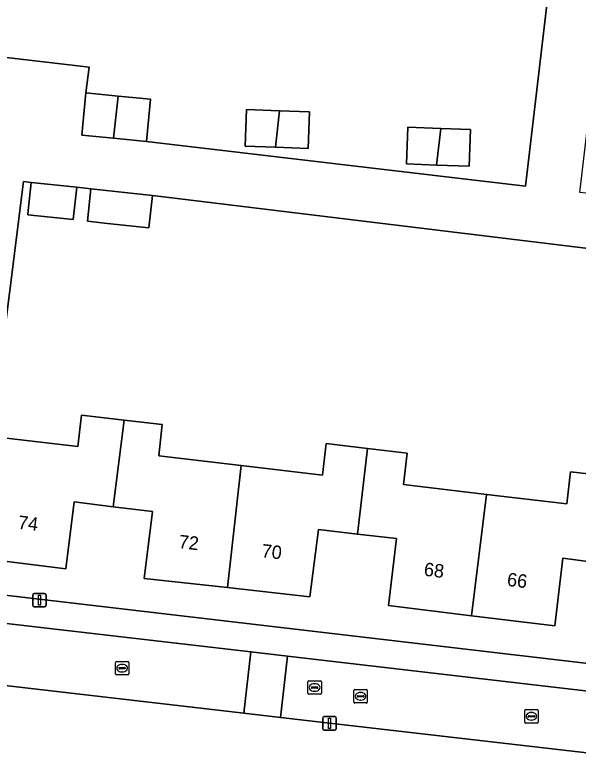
# Model space of a CAD drawing. Extents: x 161241 to 161758, y 384138 to 384885.
# Drawn here: x 161418.6 to 161460.5, y 384342.9 to 384397.6 of the extents above; entities that cross this region are included whole.
import ezdxf

# ---------------------------------------------------------------- set-up
doc = ezdxf.new("R2010")
doc.units = 0
for name, color, linetype in [('IMGEO_Erf', 7, 'Continuous'), ('IMGEO_Kolk', 7, 'Continuous'), ('IMGEO_Lichtmast', 7, 'Continuous'), ('IMGEO_Pand', 7, 'Continuous'), ('IMGEO_Pand_nummerreeks', 7, 'Continuous'), ('IMGEO_Rijbaan_lokaal_open', 7, 'Continuous'), ('IMGEO_Rioolput', 7, 'Continuous'), ('IMGEO_Voetpad_open', 7, 'Continuous')]:
    doc.layers.add(name, color=color, linetype=linetype)

msp = doc.modelspace()

# ---------------------------------------------------------------- linework, layer by layer
at = {"layer": 'IMGEO_Erf'}
for points in [[(161415.847, 384394.67), (161424.15, 384393.701), (161423.913, 384391.799), (161426.306, 384391.565), (161428.717, 384391.33), (161428.41, 384388.19), (161456.596, 384384.852), (161460.391, 384417.148), (161459.347, 384417.271), (161457.727, 384415.687), (161417.974, 384420.297)], [(161472.875, 384378.82), (161428.856, 384384.157), (161428.597, 384381.761), (161425.529, 384382.092), (161424.024, 384382.255), (161424.284, 384384.664), (161423.233, 384384.777), (161422.973, 384382.369), (161419.593, 384382.735), (161419.599, 384382.791), (161419.853, 384385.142), (161419.263, 384385.217), (161417.156, 384368.588)], [(161417.35, 384366.195), (161423.302, 384365.497), (161423.576, 384367.831), (161426.756, 384367.458), (161429.595, 384367.125), (161429.323, 384364.801), (161435.447, 384364.083), (161441.5, 384363.373), (161441.774, 384365.707), (161444.836, 384365.348), (161447.793, 384365.001), (161447.518, 384362.658), (161453.697, 384361.933), (161459.665, 384361.233), (161459.945, 384363.617), (161463.005, 384363.258)], [(161464.974, 384356.457), (161462.172, 384356.819), (161459.371, 384357.18), (161458.786, 384352.151), (161452.591, 384352.91), (161446.419, 384353.667), (161447.01, 384358.643), (161444.102, 384358.98), (161441.194, 384359.316), (161440.559, 384354.315), (161434.437, 384354.996), (161428.239, 384355.685), (161428.857, 384360.656), (161425.952, 384361.017), (161423.051, 384361.378), (161422.432, 384356.406), (161416.255, 384357.153)], [(161394.009, 384357.23), (161490.429, 384345.932)], [(161464.362, 384342.323), (161438.38, 384345.338), (161435.648, 384345.655), (161391.147, 384350.82), (161389.324, 384351.032), (161386.343, 384326.184)]]:
    msp.add_lwpolyline(points, dxfattribs=at)
for points in [[(161440.426, 384387.665), (161438.007, 384387.754), (161435.762, 384387.838), (161435.863, 384390.564), (161438.314, 384390.473), (161440.527, 384390.391)], [(161449.988, 384386.426), (161447.743, 384386.51), (161447.844, 384389.236), (161450.295, 384389.145), (161452.508, 384389.063), (161452.407, 384386.337)]]:
    msp.add_lwpolyline(points, close=True, dxfattribs=at)
at = {"layer": 'IMGEO_Kolk'}
for p, q in [((161426.105, 384348.579), (161426.105, 384349.431)), ((161426.18, 384349.505), (161427.032, 384349.505)), ((161426.593, 384349.285), (161426.618, 384349.285)), ((161427.106, 384349.431), (161427.106, 384348.579)), ((161426.364, 384348.999), (161426.364, 384349.011)), ((161426.802, 384348.962), (161426.404, 384348.962)), ((161426.407, 384349.048), (161426.805, 384349.048)), ((161426.616, 384348.725), (161426.591, 384348.725)), ((161426.848, 384349.011), (161426.848, 384348.999)), ((161427.032, 384348.505), (161426.18, 384348.505)), ((161443.833, 384346.488), (161443.833, 384347.34)), ((161443.908, 384347.414), (161444.76, 384347.414)), ((161444.321, 384347.194), (161444.346, 384347.194)), ((161444.834, 384347.34), (161444.834, 384346.488)), ((161444.092, 384346.908), (161444.092, 384346.92)), ((161444.53, 384346.871), (161444.132, 384346.871)), ((161444.135, 384346.957), (161444.533, 384346.957)), ((161444.344, 384346.634), (161444.319, 384346.634)), ((161444.576, 384346.92), (161444.576, 384346.908)), ((161444.76, 384346.414), (161443.908, 384346.414)), ((161456.608, 384345.926), (161457.46, 384345.926)), ((161456.533, 384345), (161456.533, 384345.852)), ((161456.792, 384345.42), (161456.792, 384345.432)), ((161457.23, 384345.383), (161456.832, 384345.383)), ((161456.835, 384345.469), (161457.233, 384345.469)), ((161457.021, 384345.706), (161457.046, 384345.706)), ((161457.276, 384345.432), (161457.276, 384345.42)), ((161457.534, 384345.852), (161457.534, 384345)), ((161457.46, 384344.926), (161456.608, 384344.926)), ((161457.044, 384345.146), (161457.019, 384345.146))]:
    msp.add_line(p, q, dxfattribs=at)
for points in [[(161426.105, 384348.579), (161426.105, 384349.431)], [(161426.18, 384349.505), (161427.032, 384349.505)], [(161427.106, 384349.431), (161427.106, 384348.579)], [(161427.032, 384348.505), (161426.18, 384348.505)], [(161443.833, 384346.488), (161443.833, 384347.34)], [(161443.908, 384347.414), (161444.76, 384347.414)], [(161444.834, 384347.34), (161444.834, 384346.488)], [(161444.76, 384346.414), (161443.908, 384346.414)], [(161456.608, 384345.926), (161457.46, 384345.926)], [(161456.533, 384345), (161456.533, 384345.852)], [(161457.534, 384345.852), (161457.534, 384345)], [(161457.46, 384344.926), (161456.608, 384344.926)]]:
    msp.add_lwpolyline(points, dxfattribs=at)
for centre, radius, start, end in [((161426.182, 384349.429), 0.0765, 91.552, 178.448), ((161426.182, 384349.429), 0.0765, 91.552, 178.448), ((161427.03, 384349.429), 0.0765, 1.552, 88.448), ((161427.03, 384349.429), 0.0765, 1.552, 88.448), ((161426.404, 384349.008), 0.0403, 85.8775, 175.7526), ((161426.401, 384348.998), 0.0366, 178.938, 274.7102), ((161426.805, 384349.005), 0.043, 264.8664, 352.4533), ((161426.809, 384349.01), 0.0386, 1.7309, 96.639), ((161426.182, 384348.581), 0.0765, 181.552, 268.448), ((161426.182, 384348.581), 0.0765, 181.552, 268.448), ((161427.03, 384348.581), 0.0765, 271.552, 358.448), ((161427.03, 384348.581), 0.0765, 271.552, 358.448), ((161443.91, 384347.338), 0.0765, 91.552, 178.448), ((161443.91, 384347.338), 0.0765, 91.552, 178.448), ((161444.758, 384347.338), 0.0765, 1.552, 88.448), ((161444.758, 384347.338), 0.0765, 1.552, 88.448), ((161443.91, 384346.49), 0.0765, 181.552, 268.448), ((161443.91, 384346.49), 0.0765, 181.552, 268.448), ((161444.132, 384346.917), 0.0403, 85.8775, 175.7526), ((161444.129, 384346.907), 0.0366, 178.938, 274.7102), ((161444.533, 384346.914), 0.043, 264.8664, 352.4533), ((161444.537, 384346.919), 0.0386, 1.7309, 96.639), ((161444.758, 384346.49), 0.0765, 271.552, 358.448), ((161444.758, 384346.49), 0.0765, 271.552, 358.448), ((161456.61, 384345.85), 0.0765, 91.552, 178.448), ((161456.61, 384345.85), 0.0765, 91.552, 178.448), ((161457.458, 384345.85), 0.0765, 1.552, 88.448), ((161457.458, 384345.85), 0.0765, 1.552, 88.448), ((161456.832, 384345.429), 0.0403, 85.8775, 175.7526), ((161456.829, 384345.419), 0.0366, 178.938, 274.7102), ((161457.233, 384345.426), 0.043, 264.8664, 352.4533), ((161457.237, 384345.431), 0.0386, 1.7309, 96.639), ((161456.61, 384345.002), 0.0765, 181.552, 268.448), ((161456.61, 384345.002), 0.0765, 181.552, 268.448), ((161457.458, 384345.002), 0.0765, 271.552, 358.448), ((161457.458, 384345.002), 0.0765, 271.552, 358.448)]:
    msp.add_arc(centre, radius, start, end, dxfattribs=at)
for centre, major_axis, ratio, start_param, end_param in [((161426.592, 384349.005), (-0.387, 0.002), 0.722429, 4.712389, 7.853982), ((161426.617, 384349.005), (-0.39, 0.002), 0.717154, 1.570796, 4.712389), ((161444.32, 384346.914), (-0.387, 0.002), 0.722429, 4.712389, 7.853982), ((161444.345, 384346.914), (-0.39, 0.002), 0.717154, 1.570796, 4.712389), ((161457.02, 384345.426), (-0.387, 0.002), 0.722429, 4.712389, 7.853982), ((161457.045, 384345.426), (-0.39, 0.002), 0.717154, 1.570796, 4.712389)]:
    msp.add_ellipse(centre, major_axis=major_axis, ratio=ratio, start_param=start_param, end_param=end_param, dxfattribs=at)
at = {"layer": 'IMGEO_Lichtmast'}
for p, q in [((161419.958, 384353.658), (161419.958, 384354.458)), ((161419.958, 384354.458), (161419.958, 384353.658)), ((161420.058, 384354.558), (161420.848, 384354.558)), ((161420.848, 384354.558), (161420.058, 384354.558)), ((161420.948, 384354.458), (161420.948, 384353.658)), ((161420.948, 384353.658), (161420.948, 384354.458)), ((161420.848, 384353.558), (161420.058, 384353.558)), ((161420.058, 384353.558), (161420.848, 384353.558)), ((161441.624, 384345.401), (161442.414, 384345.401)), ((161442.414, 384345.401), (161441.624, 384345.401)), ((161441.524, 384344.501), (161441.524, 384345.301)), ((161441.524, 384345.301), (161441.524, 384344.501)), ((161442.514, 384345.301), (161442.514, 384344.501)), ((161442.514, 384344.501), (161442.514, 384345.301)), ((161442.414, 384344.401), (161441.624, 384344.401)), ((161441.624, 384344.401), (161442.414, 384344.401))]:
    msp.add_line(p, q, dxfattribs=at)
for points in [[(161420.378, 384354.433), (161420.528, 384354.433), (161420.528, 384353.683), (161420.378, 384353.683), (161420.378, 384354.433)], [(161441.944, 384345.276), (161442.094, 384345.276), (161442.094, 384344.526), (161441.944, 384344.526), (161441.944, 384345.276)]]:
    msp.add_lwpolyline(points, dxfattribs=at)
for centre, start, end in [((161420.058, 384354.458), 90, 180), ((161420.058, 384354.458), 90, 180), ((161420.848, 384354.458), 0, 90), ((161420.848, 384354.458), 360, 90), ((161420.058, 384353.658), 180, 270), ((161420.058, 384353.658), 180, 270), ((161420.848, 384353.658), 270, 0), ((161420.848, 384353.658), 270, 0), ((161441.624, 384345.301), 90, 180), ((161441.624, 384345.301), 90, 180), ((161442.414, 384345.301), 0, 90), ((161442.414, 384345.301), 360, 90), ((161441.624, 384344.501), 180, 270), ((161441.624, 384344.501), 180, 270), ((161442.414, 384344.501), 270, 0), ((161442.414, 384344.501), 270, 0)]:
    msp.add_arc(centre, 0.1, start, end, dxfattribs=at)
at = {"layer": 'IMGEO_Pand'}
for points in [[(161426.306, 384391.565), (161423.913, 384391.799), (161423.606, 384388.659), (161425.953, 384388.43)], [(161428.717, 384391.33), (161426.306, 384391.565), (161425.953, 384388.43), (161428.41, 384388.19)], [(161435.863, 384390.564), (161435.762, 384387.838), (161438.007, 384387.754), (161438.314, 384390.473)], [(161440.426, 384387.665), (161440.527, 384390.391), (161438.314, 384390.473), (161438.007, 384387.754)], [(161447.844, 384389.236), (161447.743, 384386.51), (161449.988, 384386.426), (161450.295, 384389.145)], [(161452.407, 384386.337), (161452.508, 384389.063), (161450.295, 384389.145), (161449.988, 384386.426)], [(161423.233, 384384.777), (161419.853, 384385.142), (161419.599, 384382.791), (161419.593, 384382.735), (161422.973, 384382.369)], [(161428.856, 384384.157), (161424.284, 384384.664), (161424.024, 384382.255), (161425.529, 384382.092), (161428.597, 384381.761)], [(161416.255, 384357.153), (161422.432, 384356.406), (161423.051, 384361.378), (161425.952, 384361.017), (161426.756, 384367.458), (161423.576, 384367.831), (161423.302, 384365.497), (161417.35, 384366.195)], [(161425.952, 384361.017), (161428.857, 384360.656), (161428.239, 384355.685), (161434.437, 384354.996), (161435.447, 384364.083), (161429.323, 384364.801), (161429.595, 384367.125), (161426.756, 384367.458)], [(161444.836, 384365.348), (161441.774, 384365.707), (161441.5, 384363.373), (161435.447, 384364.083), (161434.437, 384354.996), (161440.559, 384354.315), (161441.194, 384359.316), (161444.102, 384358.98)], [(161444.102, 384358.98), (161447.01, 384358.643), (161446.419, 384353.667), (161452.591, 384352.91), (161453.697, 384361.933), (161447.518, 384362.658), (161447.793, 384365.001), (161444.836, 384365.348)], [(161463.005, 384363.258), (161459.945, 384363.617), (161459.665, 384361.233), (161453.697, 384361.933), (161452.591, 384352.91), (161458.786, 384352.151), (161459.371, 384357.18), (161462.172, 384356.819)]]:
    msp.add_lwpolyline(points, close=True, dxfattribs=at)
at = {"layer": 'IMGEO_Rijbaan_lokaal_open'}
for points in [[(161506.638, 384379.095), (161463.961, 384384), (161461.689, 384384.202), (161461.694, 384384.264), (161460.643, 384384.386), (161464.436, 384416.673), (161460.391, 384417.148), (161456.596, 384384.852), (161428.41, 384388.19), (161425.953, 384388.43), (161423.606, 384388.659), (161423.913, 384391.799), (161424.15, 384393.701), (161415.847, 384394.67)], [(161417.156, 384368.588), (161419.263, 384385.217), (161419.853, 384385.142), (161423.233, 384384.777), (161424.284, 384384.664), (161428.856, 384384.157), (161472.875, 384378.82), (161471.891, 384371.04), (161475.543, 384370.648), (161475.632, 384371.357), (161476.445, 384377.795), (161478.805, 384377.496), (161488.879, 384376.277), (161488.964, 384376.982), (161506.195, 384375.218)]]:
    msp.add_lwpolyline(points, dxfattribs=at)
for points in [[(161435.648, 384345.655), (161436.178, 384350.21), (161391.7, 384355.381), (161391.147, 384350.82)], [(161438.38, 384345.338), (161438.91, 384349.892), (161436.178, 384350.21), (161435.648, 384345.655)], [(161490.204, 384343.929), (161438.91, 384349.892), (161438.38, 384345.338), (161464.362, 384342.323), (161464.464, 384342.311), (161465.534, 384342.187), (161470.952, 384341.558), (161476.463, 384340.955), (161489.705, 384339.472)]]:
    msp.add_lwpolyline(points, close=True, dxfattribs=at)
at = {"layer": 'IMGEO_Rioolput'}
for p, q in [((161440.417, 384347.136), (161440.417, 384347.988)), ((161440.492, 384348.062), (161441.344, 384348.062)), ((161440.676, 384347.556), (161440.676, 384347.568)), ((161440.719, 384347.605), (161441.117, 384347.605)), ((161440.905, 384347.842), (161440.93, 384347.842)), ((161441.16, 384347.568), (161441.16, 384347.556)), ((161441.418, 384347.988), (161441.418, 384347.136)), ((161441.344, 384347.062), (161440.492, 384347.062)), ((161441.114, 384347.519), (161440.716, 384347.519)), ((161440.928, 384347.282), (161440.903, 384347.282))]:
    msp.add_line(p, q, dxfattribs=at)
for points in [[(161440.417, 384347.136), (161440.417, 384347.988)], [(161440.492, 384348.062), (161441.344, 384348.062)], [(161441.418, 384347.988), (161441.418, 384347.136)], [(161441.344, 384347.062), (161440.492, 384347.062)]]:
    msp.add_lwpolyline(points, dxfattribs=at)
for centre, radius, start, end in [((161440.494, 384347.986), 0.0765, 91.552, 178.448), ((161440.494, 384347.986), 0.0765, 91.552, 178.448), ((161440.716, 384347.565), 0.0403, 85.8775, 175.7526), ((161440.713, 384347.555), 0.0366, 178.938, 274.7102), ((161441.117, 384347.562), 0.043, 264.8664, 352.4533), ((161441.121, 384347.567), 0.0386, 1.7309, 96.639), ((161441.342, 384347.986), 0.0765, 1.552, 88.448), ((161441.342, 384347.986), 0.0765, 1.552, 88.448), ((161440.494, 384347.138), 0.0765, 181.552, 268.448), ((161440.494, 384347.138), 0.0765, 181.552, 268.448), ((161441.342, 384347.138), 0.0765, 271.552, 358.448), ((161441.342, 384347.138), 0.0765, 271.552, 358.448)]:
    msp.add_arc(centre, radius, start, end, dxfattribs=at)
for centre, major_axis, ratio, start_param, end_param in [((161440.904, 384347.562), (-0.387, 0.002), 0.722429, 4.712389, 7.853982), ((161440.929, 384347.562), (-0.39, 0.002), 0.717154, 1.570796, 4.712389)]:
    msp.add_ellipse(centre, major_axis=major_axis, ratio=ratio, start_param=start_param, end_param=end_param, dxfattribs=at)
at = {"layer": 'IMGEO_Voetpad_open'}
for points in [[(161392.099, 384359.279), (161391.7, 384355.381), (161436.178, 384350.21), (161438.91, 384349.892), (161490.204, 384343.929)], [(161490.429, 384345.932), (161394.009, 384357.23)]]:
    msp.add_lwpolyline(points, dxfattribs=at)

# ---------------------------------------------------------------- texts
at = {"layer": 'IMGEO_Pand_nummerreeks'}
for s, rotation, p in [('74', 353.1046, (161418.826, 384359.38)), ('72', 353.6547, (161430.774, 384357.939)), ('70', 353.6547, (161436.94, 384357.254)), ('68', 353.0113, (161449, 384355.889)), ('66', 353.0113, (161455.18, 384355.131))]:
    msp.add_text(s, height=1, rotation=rotation, dxfattribs=at).set_placement(p)

doc.saveas('drawing.dxf')
